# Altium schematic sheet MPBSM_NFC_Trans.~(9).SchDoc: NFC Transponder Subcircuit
size A3; Date: Not shown in title block; ApprovedBy: Not shown in title block; CheckedBy: Not shown in title block; Author: Not shown in title block; CompanyName: Not shown in title block; DrawnBy: Not shown in title block; Engineer: Not shown in title block; Organization: Not shown in title block; Address1: Not shown in title block; Address2: Not shown in title block; Address3: Not shown in title block; Address4: Not shown in title block; DocumentNumber: 7; Revision: Use project parameter SCH_Rev; SheetNumber: 9; SheetTotal: 12; PageSetup: Record=PageOptions¦CenterHorizontal=True¦CenterVertical=True¦PrintScale=0.69¦XCorrection=1.00¦YCorrection=1.00¦PrintKind=0¦BorderSize=5000000¦LeftOffset=0¦BottomOffset=0¦Orientation=2¦PaperLength=1000¦PaperWidth=1000¦Scale=100¦PaperSource=15¦PrintQuality=600¦MediaType=1¦DitherType=10¦PaperKind=Letter¦PrintScaleMode=1
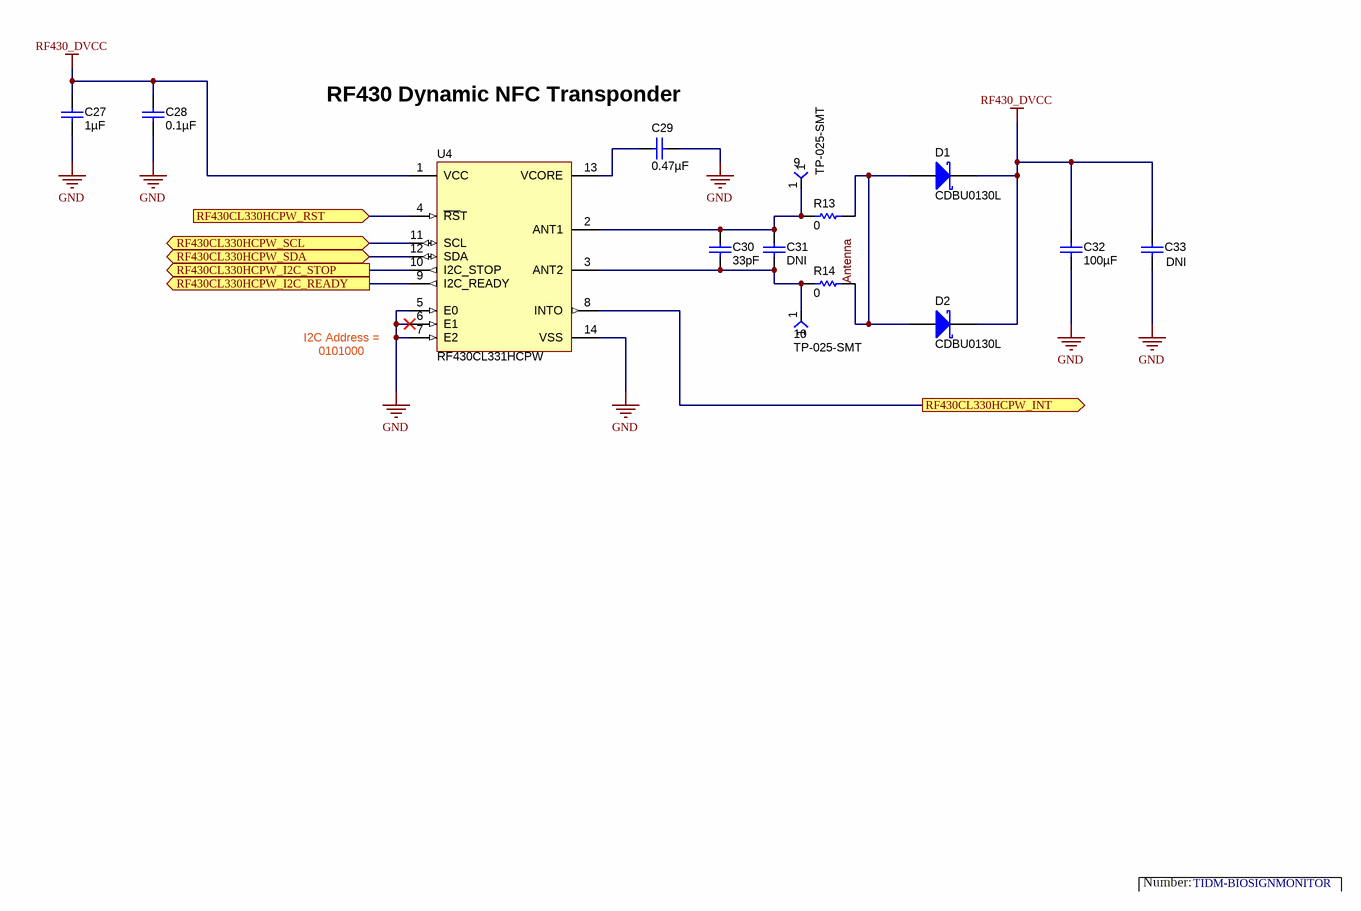
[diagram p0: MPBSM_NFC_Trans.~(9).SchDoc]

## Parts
9  TP-025-SMT  [TP_25MIL-SMT]
10  TP-025-SMT  [TP_25MIL-SMT]
C27  ValueDisplayed: 1µF  [0402]  (hidden comment: C1005X5R0J105M)
C28  ValueDisplayed: 0.1µF  [0402]  (hidden comment: C1005X5R1A104K)
C29  ValueDisplayed: 0.47µF  [0402]  (hidden comment: GRM155R60J474KE19D)
C30  ValueDisplayed: 33pF  [0603]  (hidden comment: C1608C0G1H330J)
C31  GRM1555C1H390JA01D  [0402]  (value not drawn)
C32  ValueDisplayed: 100µF  [1206_190]  (hidden comment: C3216X5R1A107M160AC)
C33  Used in BOM report  [0603]  (value not drawn)
D1  CDBU0130L  [SOD-523F]
D2  CDBU0130L  [SOD-523F]
R13  ValueDisplayed: 0  [0402]  (hidden comment: ERJ-2GE0R00X)
R14  ValueDisplayed: 0  [0402]  (hidden comment: ERJ-2GE0R00X)
U4  RF430CL331HCPW  [PW0014A_M]

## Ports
RF430CL330HCPW_I2C_READY (out), RF430CL330HCPW_I2C_STOP (out), RF430CL330HCPW_INT (out), RF430CL330HCPW_RST (in), RF430CL330HCPW_SCL (bidir), RF430CL330HCPW_SDA (bidir)

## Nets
GND: C27.2 C28.2 C29.1 C32.2 C33.2 U4.5(E0) U4.6(E1) U4.7(E2) U4.14(VSS)
RF430_DVCC: C27.1 C28.1 C32.1 C33.1 D1.1(K) D2.1(K) U4.1(VCC)
Antenna: D1.2(A) D2.2(A) R13.2 R14.2
RF430CL330HCPW_I2C_READY: U4.9(I2C_READY) ; port RF430CL330HCPW_I2C_READY
RF430CL330HCPW_I2C_STOP: U4.10(I2C_STOP) ; port RF430CL330HCPW_I2C_STOP
RF430CL330HCPW_INT: U4.8(INTO) ; port RF430CL330HCPW_INT
RF430CL330HCPW_RST: U4.4(~{RS}T) ; port RF430CL330HCPW_RST
RF430CL330HCPW_SCL: U4.11(SCL) ; port RF430CL330HCPW_SCL
RF430CL330HCPW_SDA: U4.12(SDA) ; port RF430CL330HCPW_SDA
Net9_1: 9.1 C30.1 C31.1 R13.1 U4.2(ANT1)
Net10_1: 10.1 C30.2 C31.2 R14.1 U4.3(ANT2)
NetC29_2: C29.2 U4.13(VCORE)

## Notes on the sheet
- (near C29) RF430 Dynamic NFC Transponder
- I2C Address =
- 0101000
- Number:
- TIDM-BIOSIGNMONITOR

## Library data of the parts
9 10 = TP-025-SMT: Test Point, O.025"; Manufacturer: STD; Value: STD
C27 = C1005X5R0J105M: CAP, CERM, 1 µF, 6.3 V, +/- 20%, X5R, 0402; Manufacturer: TDK; Polarized: N; CompType: Capacitor; Value: 1uF; U/M: EA; Cap_F: 0.000001; Tolerance_%: 20; ESR_ohm: 0.0079; Value1: 0.0079 ohm; VDC_V: 6.3; Value2: 6.3V; TaMin_C: -55; TaMax_C: 85
C28 = C1005X5R1A104K: CAP, CERM, 0.1 µF, 10 V, +/- 10%, X5R, 0402; Manufacturer: TDK; Polarized: N; CompType: Capacitor; Value: 0.1uF; U/M: EA; Cap_F: 0.0000001; Tolerance_%: 10; ESR_ohm: 0.0186; Value1: 0.0186 ohm; Value2: 10V; TaMin_C: -55; TaMax_C: 85
C29 = GRM155R60J474KE19D: CAP, CERM, 0.47 µF, 6.3 V, +/- 10%, X5R, 0402; Manufacturer: MuRata; Polarized: N; CompType: Capacitor; Value: 0.47uF; U/M: EA; Cap_F: 0.00000047; Tolerance_%: 10; Value1: Unknown; VDC_V: 6.3; Value2: 6.3V; TaMin_C: -55; TaMax_C: 85
C30 = C1608C0G1H330J: CAP, CERM, 33 pF, 50 V, +/- 5%, C0G/NP0, 0603; Manufacturer: TDK; Polarized: N; CompType: Capacitor; Value: 33pF; U/M: EA; Cap_F: 0.000000000033; Tolerance_%: 5; ESR_ohm: 0.2649; Value1: 0.2649 ohm; VDC_V: 50; Value2: 50V; TaMin_C: -55; TaMax_C: 125
C31 = GRM1555C1H390JA01D: CAP, CERM, 39pF, 50V, +/-5%, C0G/NP0, 0402; Manufacturer: MuRata; Polarized: N; CompType: Capacitor; U/M: EA; Cap_F: 0.000000000039; Tolerance_%: 5; Value1: Unknown; VDC_V: 50; TaMin_C: -55; TaMax_C: 125
C32 = C3216X5R1A107M160AC: CAP, CERM, 100 µF, 10 V, +/- 20%, X5R, 1206_190; Manufacturer: TDK; Polarized: N; CompType: Capacitor; Value: 100uF; U/M: EA; Cap_F: 0.0001; Tolerance_%: 20; Value1: Unknown; VDC_V: 10; Value2: 10V; TaMin_C: -55; TaMax_C: 85
C33 = Capacitor: CAP, CERM, xxxF, xxV, [TempCo], xx%, [PackageReference]; Polarized: N; Value: Not Applicable; U/M: EA
D1 D2 = CDBU0130L: Diode, Schottky, 35V, 0.1A, SOD-523F; Manufacturer: Comchip Technology; U/M: EA; Value2: V; Io_A: 0.1; Vr_V: 35; TJmax_C: 125
R13 R14 = ERJ-2GE0R00X: RES, 0, 5%, 0.063 W, 0402; Manufacturer: Panasonic; CompType: Resistor; Value: 0; Value_Code: 0000; Tolerance_%: 5; Power_W: 0.063; Value2: 0.063W; VDC_V: 50; TempCo: 600 ppm/C; EIA_Code: E24; U/M: EA
U4 = RF430CL331H: The Texas Instruments Dynamic NFC Interface Transponder RF430CL331H is an NFC Tag Type 4 device  that combines a wireless NFC interface and a wired SPI or I2C interface to connect the device to a host.; Alternate PartNumber: RF430CL330HCPW; SymbolCreator: a0272897; CompType: IC; U/M: EA, IN, or GM; SupplyVoltageMax_V: 3.6V; SupplyVoltageMin_V: 2 V; SupplyVoltage: 2 V - 3.6 V; SupplyCurrent: 250 uA; TaMax_C: 85 °C; TaMin_C: -40 °C; Value: Mixed-Signal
